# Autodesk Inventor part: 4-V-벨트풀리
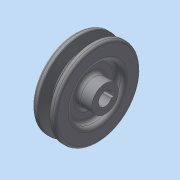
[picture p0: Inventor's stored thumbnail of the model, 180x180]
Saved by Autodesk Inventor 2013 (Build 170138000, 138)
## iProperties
Created: 2015-02
Part Number: 4-V-벨트풀리
Material: 일반
Document SubType Name: Modeling
Designer: Administrator
Density: 1 g/cm^3
Author: Administrator
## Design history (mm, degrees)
sketch "스케치1"
  geometry: L1 (0, 0)-(25, 0); L2 (0, 5.5)-(25, 5.5); L3 (25, 5.5)-(25, 11); L4 (25, 11)-(13, 11); L5 (13, 11)-(13, 21.5); L6 (13, 21.5)-(19, 21.5); L7 (19, 21.5)-(19, 35.2); L8 (19, 35.2)-(14.325, 35.2); L9 (14.325, 35.2)-(11.574, 26.2); L10 (11.574, 26.2)-(7.426, 26.2); L11 (7.426, 26.2)-(4.675, 35.2); L12 (4.675, 35.2)-(0, 35.2); L13 (0, 35.2)-(0, 21.5); L14 (0, 21.5)-(6, 21.5); L15 (6, 21.5)-(6, 11); L16 (6, 11)-(0, 11); L17 (0, 11)-(0, 5.5); 2 further points
  constraints: 34 end point, 13 parallel, 4 collinear, 3 equal length, 2 point on line, 2 vertical alignment, 1 horizontal, 1 horizontal alignment, 1 perpendicular
  dimensions: "d0" = 25 distance of L1.start L1.end; "d1" = 11 diameter of L2 L1; "d2" = 6 distance between parallel lines of L7 L5; "d3" = 8 distance of point (13.5, 32.5) point (5.5, 32.5); "d4" = 2.7 distance from line of L12 point (5.5, 32.5); "d5" = 6.3 distance from line of L10 point (5.5, 32.5); "d6" = 34 deg angle of L9 L11; "d7" = 19 distance between parallel lines of L7 L13; "d8" = 22 diameter of L4 L1; "d9" = 43 diameter of L14 L1; "d10" = 65 diameter of point (5.5, 32.5) L1
revolve "회전1" sketch "스케치1" stored, may be unused: angle "d11" = 90 deg
sketch "스케치2"
  geometry: L1 (-2, 5.123)-(-2, 7.3); L2 (-2, 7.3)-(2, 7.3); L3 (2, 7.3)-(2, 5.123); A1 r 5.5 centre (0, 0) between (-2, 5.123) and (2, 5.123) reference
  constraints: 6 end point, 2 parallel, 2 point on circle, 1 perpendicular, 1 vertical
  dimensions: "d12" = 12.8 dimension on A1 L2; "d13" = 4 distance of L1.end L2.end
extrude "돌출1" cut sketch "스케치2" stored distance "d14" = 10; taper "d15" = 0 deg
fillet "모깎기1" dims "d16" = 2, "d17" = 0.5, "d18" = 1
fillet "모깎기2" dims "d19" = 3
node "솔리드1"
